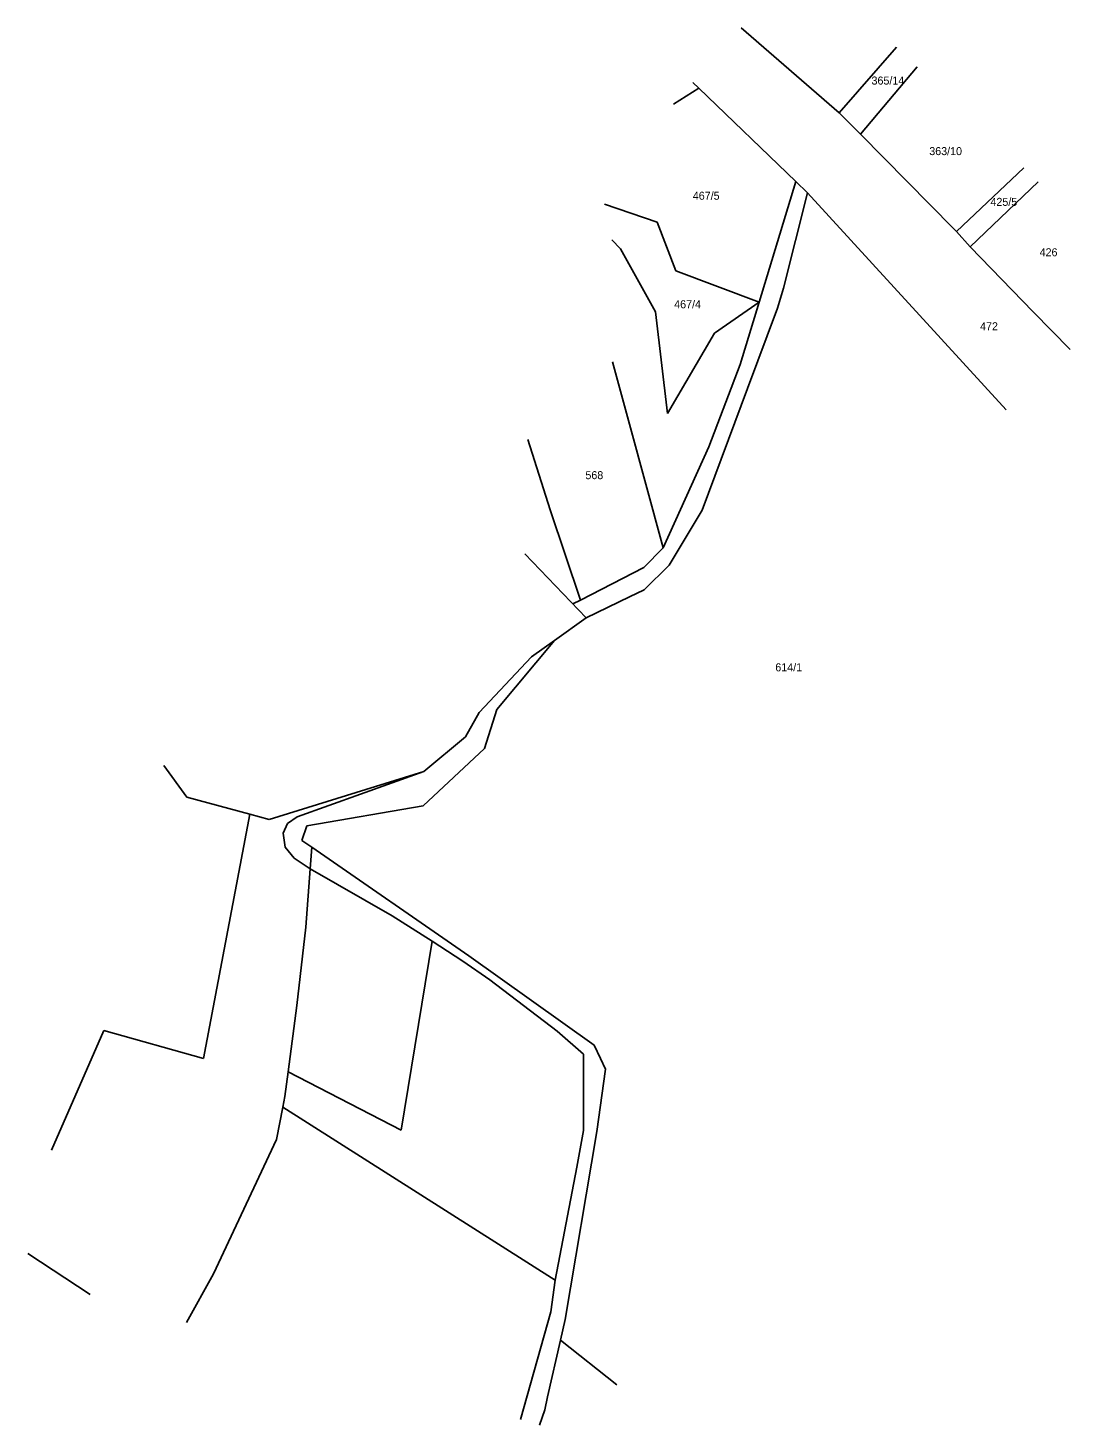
# Model space of a CAD drawing. Extents: x 4632591 to 4653165, y 5351032 to 5369868.
# Drawn here: x 4646188.8 to 4646423.3, y 5357018.5 to 5357332.8 of the extents above; entities that cross this region are included whole.
import ezdxf

# ---------------------------------------------------------------- set-up
doc = ezdxf.new("R2010")
doc.units = 0
doc.layers.add('EDZPD_211', color=7, linetype='Continuous')
doc.layers.add('EDZPD_219', color=7, linetype='Continuous')

msp = doc.modelspace()

# ---------------------------------------------------------------- linework, layer by layer
at = {"layer": 'EDZPD_219'}
for p, q in [((4646349.25, 5357332.83), (4646371.31, 5357313.71)), ((4646371.31, 5357313.71), (4646384.22, 5357328.49)), ((4646388.86, 5357324.08), (4646376.13, 5357308.95)), ((4646339.74, 5357319.3), (4646338.4, 5357320.59)), ((4646339.74, 5357319.3), (4646334.08, 5357315.71)), ((4646361.57, 5357298.25), (4646339.74, 5357319.3)), ((4646371.31, 5357313.71), (4646376.13, 5357308.95)), ((4646376.13, 5357308.95), (4646397.06, 5357287.72)), ((4646412.87, 5357301.32), (4646397.75, 5357287.01)), ((4646353.32, 5357271.17), (4646361.57, 5357298.25)), ((4646364.19, 5357295.71), (4646358.8, 5357274.27)), ((4646364.19, 5357295.71), (4646361.57, 5357298.25)), ((4646408.92, 5357246.91), (4646364.19, 5357295.71)), ((4646416.12, 5357298.24), (4646400.77, 5357283.57)), ((4646330.41, 5357289.16), (4646318.55, 5357293.18)), ((4646334.6, 5357278.19), (4646330.41, 5357289.16)), ((4646397.06, 5357287.72), (4646397.75, 5357287.01)), ((4646397.75, 5357287.01), (4646400.77, 5357283.57)), ((4646320.21, 5357285.15), (4646322.14, 5357283.17)), ((4646322.14, 5357283.17), (4646329.97, 5357268.98)), ((4646400.77, 5357283.57), (4646414.95, 5357268.98)), ((4646353.32, 5357271.17), (4646334.6, 5357278.19)), ((4646358.8, 5357274.27), (4646357.45, 5357269.75)), ((4646343.29, 5357264.17), (4646353.32, 5357271.17)), ((4646349.05, 5357257.14), (4646353.32, 5357271.17)), ((4646329.97, 5357268.98), (4646332.69, 5357246.08)), ((4646357.45, 5357269.75), (4646350.73, 5357251.72)), ((4646414.95, 5357268.98), (4646423.26, 5357260.46)), ((4646332.69, 5357246.08), (4646343.29, 5357264.17)), ((4646324.16, 5357243.68), (4646320.35, 5357257.69)), ((4646341.98, 5357238.59), (4646349.05, 5357257.14)), ((4646350.73, 5357251.72), (4646340.52, 5357224.33)), ((4646331.72, 5357215.88), (4646324.16, 5357243.68)), ((4646306.3, 5357224.44), (4646301.28, 5357240.23)), ((4646331.72, 5357215.88), (4646341.98, 5357238.59)), ((4646313.1, 5357204.1), (4646306.3, 5357224.44)), ((4646340.52, 5357224.33), (4646333.09, 5357211.95)), ((4646314.43, 5357200.09), (4646300.63, 5357214.49)), ((4646327.4, 5357211.41), (4646331.72, 5357215.88)), ((4646313.1, 5357204.1), (4646327.4, 5357211.41)), ((4646333.09, 5357211.95), (4646327.42, 5357206.45)), ((4646324.19, 5357204.87), (4646314.43, 5357200.09)), ((4646327.42, 5357206.45), (4646324.19, 5357204.87)), ((4646311.41, 5357203.24), (4646313.1, 5357204.1)), ((4646314.43, 5357200.09), (4646307.32, 5357195.03)), ((4646294.32, 5357179.51), (4646307.32, 5357195.03)), ((4646307.32, 5357195.03), (4646302.08, 5357191.31)), ((4646302.08, 5357191.31), (4646290.32, 5357178.79)), ((4646291.57, 5357170.72), (4646294.32, 5357179.51)), ((4646290.32, 5357178.79), (4646287.24, 5357173.32)), ((4646287.24, 5357173.32), (4646277.87, 5357165.54)), ((4646277.72, 5357157.8), (4646291.57, 5357170.72)), ((4646224.56, 5357159.8), (4646219.42, 5357166.87)), ((4646277.87, 5357165.54), (4646243.14, 5357154.73)), ((4646277.87, 5357165.54), (4646249.37, 5357155.36)), ((4646238.78, 5357155.92), (4646224.56, 5357159.8)), ((4646251.61, 5357153.34), (4646277.72, 5357157.8)), ((4646238.78, 5357155.92), (4646228.37, 5357100.99)), ((4646243.14, 5357154.73), (4646238.78, 5357155.92)), ((4646247.24, 5357153.84), (4646249.37, 5357155.36)), ((4646246.29, 5357151.7), (4646247.24, 5357153.84)), ((4646246.68, 5357148.51), (4646246.29, 5357151.7)), ((4646250.48, 5357150.05), (4646251.61, 5357153.34)), ((4646248.7, 5357146.03), (4646246.68, 5357148.51)), ((4646252.7, 5357148.51), (4646250.48, 5357150.05)), ((4646252.7, 5357148.51), (4646252.33, 5357143.65)), ((4646288.05, 5357124.1), (4646252.7, 5357148.51)), ((4646252.33, 5357143.65), (4646248.7, 5357146.03)), ((4646251.34, 5357130.51), (4646252.33, 5357143.65)), ((4646252.33, 5357143.65), (4646270.81, 5357133.09)), ((4646279.77, 5357127.34), (4646270.81, 5357133.09)), ((4646249.32, 5357112.93), (4646251.34, 5357130.51)), ((4646272.83, 5357084.85), (4646279.77, 5357127.34)), ((4646286.69, 5357122.88), (4646279.77, 5357127.34)), ((4646292.72, 5357118.68), (4646286.69, 5357122.88)), ((4646316.21, 5357103.97), (4646288.05, 5357124.1)), ((4646307.92, 5357107.09), (4646292.72, 5357118.68)), ((4646247.38, 5357097.99), (4646249.32, 5357112.93)), ((4646205.89, 5357107.26), (4646194.16, 5357080.35)), ((4646228.37, 5357100.99), (4646205.89, 5357107.26)), ((4646313.8, 5357101.95), (4646307.92, 5357107.09)), ((4646317.64, 5357100.97), (4646316.21, 5357103.97)), ((4646313.81, 5357092.26), (4646313.8, 5357101.95)), ((4646318.78, 5357098.56), (4646317.64, 5357100.97)), ((4646246.66, 5357092.45), (4646247.38, 5357097.99)), ((4646247.38, 5357097.99), (4646272.83, 5357084.85)), ((4646316.81, 5357084.55), (4646318.78, 5357098.56)), ((4646246.19, 5357090.04), (4646246.66, 5357092.45)), ((4646313.82, 5357084.75), (4646313.81, 5357092.26)), ((4646244.73, 5357082.73), (4646246.19, 5357090.04)), ((4646246.19, 5357090.04), (4646307.47, 5357051.09)), ((4646230.57, 5357052.5), (4646244.73, 5357082.73)), ((4646309.65, 5357042.26), (4646316.81, 5357084.55)), ((4646312.33, 5357076.56), (4646313.82, 5357084.75)), ((4646307.47, 5357051.09), (4646312.33, 5357076.56)), ((4646188.85, 5357057.11), (4646202.83, 5357047.88)), ((4646224.53, 5357041.57), (4646230.57, 5357052.5)), ((4646306.45, 5357044.01), (4646307.47, 5357051.09)), ((4646299.63, 5357019.75), (4646306.45, 5357044.01)), ((4646308.61, 5357037.62), (4646309.65, 5357042.26)), ((4646305.75, 5357024.82), (4646308.61, 5357037.62)), ((4646308.63, 5357037.61), (4646321.33, 5357027.59)), ((4646305.11, 5357021.95), (4646305.75, 5357024.82)), ((4646303.93, 5357018.51), (4646305.11, 5357021.95))]:
    msp.add_line(p, q, dxfattribs=at)

# ---------------------------------------------------------------- texts
at = {"layer": 'EDZPD_211'}
for s, p in [('365/14', (4646378.6, 5357320.09)), ('363/10', (4646391.59, 5357304.22)), ('467/5', (4646338.4, 5357294.18)), ('425/5', (4646405.35, 5357292.8)), ('426', (4646416.41, 5357281.46)), ('467/4', (4646334.21, 5357269.76)), ('472', (4646403.02, 5357264.82)), ('568', (4646314.24, 5357231.31)), ('614/1', (4646356.96, 5357188.08))]:
    msp.add_text(s, height=1.8, dxfattribs=at).set_placement(p)

doc.saveas('drawing.dxf')
